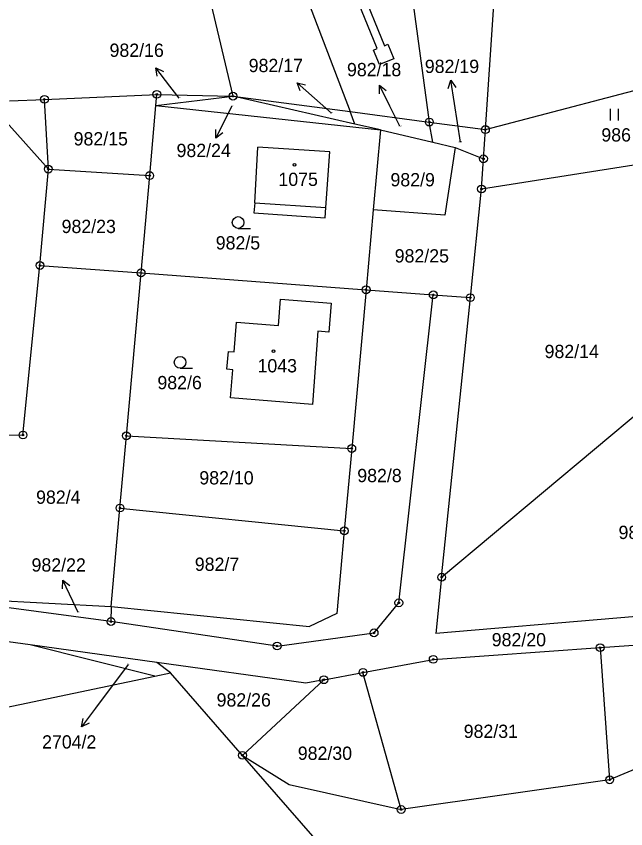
# Model space of a CAD drawing. Extents: x -439246 to -433691, y -1130252 to -1121148.
# Drawn here: x -438051.1 to -437973, y -1124320.3 to -1124216.2 of the extents above; entities that cross this region are included whole.
import ezdxf

# ---------------------------------------------------------------- set-up
doc = ezdxf.new("R2010")
doc.units = 0
for name, color, linetype in [('Vrstva 1', 7, 'Continuous'), ('Vrstva 16', 7, 'Continuous'), ('Vrstva 18', 7, 'Continuous'), ('Vrstva 19', 7, 'Continuous'), ('Vrstva 24', 7, 'Continuous'), ('Vrstva 25', 7, 'Continuous'), ('Vrstva 3', 7, 'Continuous'), ('Vrstva 30', 7, 'Continuous'), ('Vrstva 37', 7, 'Continuous'), ('Vrstva 4', 7, 'Continuous')]:
    doc.layers.add(name, color=color, linetype=linetype)

msp = doc.modelspace()

# ---------------------------------------------------------------- linework, layer by layer
at = {"layer": 'Vrstva 1'}
for points in [[(-438022.56, -1124191.1), (-438008.31, -1124228.46)], [(-438002.2, -1124200.19), (-437998.18, -1124229.8)], [(-437990.99, -1124230.76), (-437988.95, -1124200.08)], [(-438027.12, -1124210.42), (-438023.32, -1124226.48)], [(-437990.99, -1124230.76), (-437965.91, -1124224.17)], [(-438047.47, -1124226.89), (-438033.08, -1124226.25)], [(-438033.2, -1124227.68), (-438033.08, -1124226.25)], [(-438033.2, -1124227.68), (-438023.32, -1124226.48)], [(-438033.08, -1124226.25), (-438023.32, -1124226.48)], [(-438023.32, -1124226.48), (-438008.31, -1124228.46)], [(-438007.7, -1124230.07), (-438023.32, -1124226.48)], [(-438051.94, -1124227.09), (-438047.47, -1124226.89)], [(-438046.97, -1124235.82), (-438047.47, -1124226.89)], [(-438033.99, -1124236.65), (-438033.2, -1124227.68)], [(-438033.2, -1124227.68), (-438004.42, -1124230.8)], [(-438007.7, -1124230.07), (-438008.31, -1124228.46)], [(-438008.31, -1124228.46), (-437998.18, -1124229.8)], [(-438046.97, -1124235.82), (-438053.08, -1124228.96)], [(-437998.18, -1124229.8), (-437990.99, -1124230.76)], [(-437997.73, -1124232.39), (-437998.18, -1124229.8)], [(-438004.42, -1124230.8), (-438007.7, -1124230.07)], [(-438004.42, -1124230.8), (-438005.35, -1124241.04)], [(-438004.42, -1124230.8), (-437997.73, -1124232.39)], [(-437991.24, -1124234.5), (-437990.99, -1124230.76)], [(-438020.54, -1124240.14), (-438020.13, -1124233)], [(-438010.93, -1124233.62), (-438020.13, -1124233)], [(-437997.73, -1124232.39), (-437994.88, -1124233.07)], [(-438011.41, -1124240.75), (-438010.93, -1124233.62)], [(-437994.88, -1124233.07), (-437996.18, -1124241.7)], [(-437994.88, -1124233.07), (-437991.24, -1124234.5)], [(-437991.49, -1124238.36), (-437960.31, -1124233.42)], [(-437991.49, -1124238.36), (-437991.24, -1124234.5)], [(-438048.04, -1124248.16), (-438046.97, -1124235.82)], [(-438046.97, -1124235.82), (-438033.99, -1124236.65)], [(-438035.09, -1124249.11), (-438033.99, -1124236.65)], [(-437992.92, -1124252.28), (-437991.49, -1124238.36)], [(-438020.54, -1124240.14), (-438020.63, -1124241.44)], [(-438011.5, -1124242.05), (-438011.41, -1124240.75)], [(-438005.35, -1124241.04), (-438006.27, -1124251.27)], [(-437996.18, -1124241.7), (-438005.35, -1124241.04)], [(-438020.63, -1124241.44), (-438011.5, -1124242.05)], [(-438050.22, -1124269.87), (-438048.04, -1124248.16)], [(-438048.04, -1124248.16), (-438035.09, -1124249.11)], [(-438036.97, -1124269.97), (-438035.09, -1124249.11)], [(-438035.09, -1124249.11), (-438006.27, -1124251.27)], [(-438006.27, -1124251.27), (-438008.11, -1124271.59)], [(-438006.27, -1124251.27), (-437997.67, -1124251.92)], [(-438017.5, -1124255.86), (-438017.22, -1124252.47)], [(-438017.22, -1124252.47), (-438010.74, -1124253)], [(-438002.08, -1124291.36), (-437997.67, -1124251.92)], [(-437997.67, -1124251.92), (-437992.92, -1124252.28)], [(-437996.6, -1124288.08), (-437992.92, -1124252.28)], [(-438010.74, -1124253), (-438011.05, -1124256.69)], [(-438023.15, -1124259.23), (-438022.88, -1124255.41)], [(-438022.88, -1124255.41), (-438017.5, -1124255.86)], [(-438012.44, -1124256.58), (-438013.13, -1124265.98)], [(-438011.05, -1124256.69), (-438012.44, -1124256.58)], [(-438024.09, -1124261.46), (-438023.9, -1124259.17)], [(-438023.9, -1124259.17), (-438023.15, -1124259.23)], [(-437996.6, -1124288.08), (-437963.96, -1124260.77)], [(-438023.34, -1124261.52), (-438024.09, -1124261.46)], [(-438023.64, -1124265.11), (-438023.34, -1124261.52)], [(-438013.13, -1124265.98), (-438023.64, -1124265.11)], [(-438072.38, -1124269.7), (-438050.22, -1124269.87)], [(-438037.8, -1124279.22), (-438036.97, -1124269.97)], [(-438036.97, -1124269.97), (-438008.11, -1124271.59)], [(-438008.11, -1124271.59), (-438009.06, -1124282.14)], [(-438038.93, -1124291.82), (-438037.8, -1124279.22)], [(-438037.8, -1124279.22), (-438009.06, -1124282.14)], [(-438009.06, -1124282.14), (-438010.02, -1124292.71)], [(-437996.6, -1124288.08), (-437997.33, -1124295.28)], [(-438038.95, -1124293.76), (-438062.93, -1124290.56)], [(-438062.93, -1124290.56), (-438038.93, -1124291.82)], [(-438038.93, -1124291.82), (-438038.95, -1124293.76)], [(-438038.93, -1124291.82), (-438013.54, -1124294.38)], [(-438005.25, -1124295.21), (-438002.08, -1124291.36)], [(-437950.96, -1124291.38), (-437997.33, -1124295.28)], [(-438010.02, -1124292.71), (-438013.54, -1124294.38)], [(-438049.3, -1124296.75), (-438071.18, -1124293.73)], [(-438017.67, -1124296.89), (-438038.95, -1124293.76)], [(-438017.67, -1124296.89), (-438005.25, -1124295.21)], [(-437976.29, -1124297.1), (-437949.33, -1124295.21)], [(-438033.34, -1124300.75), (-438049.3, -1124296.75)], [(-438033.06, -1124299), (-438049.3, -1124296.75)], [(-437997.67, -1124298.6), (-437976.29, -1124297.1)], [(-437976.29, -1124297.1), (-437975.08, -1124314.02)], [(-438006.67, -1124300.27), (-437997.67, -1124298.6)], [(-438031.34, -1124300.33), (-438033.06, -1124299)], [(-438014.01, -1124301.63), (-438033.06, -1124299)], [(-438033.34, -1124300.75), (-438031.34, -1124300.33)], [(-438022.11, -1124310.89), (-438031.34, -1124300.33)], [(-438011.68, -1124301.21), (-438006.67, -1124300.27)], [(-438001.78, -1124317.82), (-438006.67, -1124300.27)], [(-438079.16, -1124310.36), (-438033.34, -1124300.75)], [(-438022.11, -1124310.89), (-438011.68, -1124301.21)], [(-438011.68, -1124301.21), (-438014.01, -1124301.63)], [(-437950.19, -1124303.61), (-437975.08, -1124314.02)], [(-437993.94, -1124343.22), (-438022.11, -1124310.89)], [(-438022.11, -1124310.89), (-438016.12, -1124314.61)], [(-437975.08, -1124314.02), (-438001.78, -1124317.82)], [(-438016.12, -1124314.61), (-438001.78, -1124317.82)]]:
    msp.add_lwpolyline(points, dxfattribs=at)
at = {"layer": 'Vrstva 16'}
for p, q in [((-438031.39, -1124225.22), (-438033.22, -1124222.84)), ((-437994.97, -1124227.41), (-437995.42, -1124224.44)), ((-438012.87, -1124226.75), (-438015.12, -1124224.76)), ((-438003.23, -1124227.77), (-438004.57, -1124225.09)), ((-438024.18, -1124229.16), (-438025.52, -1124231.84)), ((-438043.83, -1124291.16), (-438045.11, -1124288.45)), ((-438040.93, -1124304.86), (-438042.73, -1124307.26))]:
    msp.add_line(p, q, dxfattribs=at)
for points in [[(-438033.01, -1124223.94), (-438033.22, -1124222.84), (-438032.21, -1124223.33)], [(-437995.77, -1124225.51), (-437995.42, -1124224.44), (-437994.78, -1124225.36)], [(-438030.22, -1124226.75), (-438031.39, -1124225.22)], [(-438014.7, -1124225.8), (-438015.12, -1124224.76), (-438014.04, -1124225.05)], [(-438004.57, -1124226.2), (-438004.57, -1124225.09), (-438003.68, -1124225.76)], [(-438010.71, -1124228.67), (-438012.87, -1124226.75)], [(-438023.48, -1124227.75), (-438024.18, -1124229.16)], [(-438001.94, -1124230.33), (-438003.23, -1124227.77)], [(-437994.2, -1124232.38), (-437994.97, -1124227.41)], [(-438024.63, -1124231.17), (-438025.52, -1124231.84), (-438025.52, -1124230.73)], [(-438045.14, -1124289.57), (-438045.11, -1124288.45), (-438044.23, -1124289.14)], [(-438043.15, -1124292.58), (-438043.83, -1124291.16)], [(-438036.73, -1124299.25), (-438040.93, -1124304.86)], [(-438041.73, -1124306.76), (-438042.73, -1124307.26), (-438042.53, -1124306.16)]]:
    msp.add_lwpolyline(points, dxfattribs=at)
at = {"layer": 'Vrstva 24'}
for centre, radius in [((-438033.08, -1124226.25), 0.5), ((-438047.47, -1124226.89), 0.5), ((-438047.47, -1124226.89), 0.1), ((-438033.08, -1124226.25), 0.1), ((-438023.32, -1124226.48), 0.5), ((-438023.32, -1124226.48), 0.1), ((-437998.18, -1124229.8), 0.5), ((-437998.18, -1124229.8), 0.1), ((-437990.99, -1124230.76), 0.5), ((-437990.99, -1124230.76), 0.1), ((-437991.24, -1124234.5), 0.5), ((-437991.24, -1124234.5), 0.1), ((-438046.97, -1124235.82), 0.5), ((-438046.97, -1124235.82), 0.1), ((-438033.99, -1124236.65), 0.5), ((-438033.99, -1124236.65), 0.1), ((-437991.49, -1124238.36), 0.5), ((-437991.49, -1124238.36), 0.1), ((-438048.04, -1124248.16), 0.5), ((-438048.04, -1124248.16), 0.1), ((-438035.09, -1124249.11), 0.5), ((-438035.09, -1124249.11), 0.1), ((-438006.27, -1124251.27), 0.5), ((-438006.27, -1124251.27), 0.1), ((-437997.67, -1124251.92), 0.5), ((-437992.92, -1124252.28), 0.5), ((-437997.67, -1124251.92), 0.1), ((-437992.92, -1124252.28), 0.1), ((-438050.22, -1124269.87), 0.5), ((-438036.97, -1124269.97), 0.5), ((-438050.22, -1124269.87), 0.1), ((-438036.97, -1124269.97), 0.1), ((-438008.11, -1124271.59), 0.5), ((-438008.11, -1124271.59), 0.1), ((-438037.8, -1124279.22), 0.5), ((-438037.8, -1124279.22), 0.1), ((-438009.06, -1124282.14), 0.5), ((-438009.06, -1124282.14), 0.1), ((-437996.6, -1124288.08), 0.5), ((-437996.6, -1124288.08), 0.1), ((-438002.08, -1124291.36), 0.5), ((-438002.08, -1124291.36), 0.1), ((-438038.95, -1124293.76), 0.5), ((-438038.95, -1124293.76), 0.1), ((-438005.25, -1124295.21), 0.5), ((-438005.25, -1124295.21), 0.1), ((-438017.67, -1124296.89), 0.5), ((-438017.67, -1124296.89), 0.1), ((-437976.29, -1124297.1), 0.5), ((-437976.29, -1124297.1), 0.1), ((-437997.67, -1124298.6), 0.5), ((-437997.67, -1124298.6), 0.1), ((-438006.67, -1124300.27), 0.5), ((-438006.67, -1124300.27), 0.1), ((-438011.68, -1124301.21), 0.5), ((-438011.68, -1124301.21), 0.1), ((-438022.11, -1124310.89), 0.5), ((-438022.11, -1124310.89), 0.1), ((-437975.08, -1124314.02), 0.5), ((-437975.08, -1124314.02), 0.1), ((-438001.78, -1124317.82), 0.5), ((-438001.78, -1124317.82), 0.1)]:
    msp.add_circle(centre, radius, dxfattribs=at)
at = {"layer": 'Vrstva 25'}
for p, q in [((-437974.95, -1124229.59), (-437974.95, -1124228.09)), ((-437973.95, -1124229.59), (-437973.95, -1124228.09)), ((-438022.66, -1124243.41), (-438021.06, -1124243.41)), ((-438030.09, -1124261.31), (-438028.49, -1124261.31))]:
    msp.add_line(p, q, dxfattribs=at)
for centre, radius in [((-438015.43, -1124235.28), 0.175), ((-438022.66, -1124242.66), 0.75), ((-438018.12, -1124259.15), 0.175), ((-438030.09, -1124260.56), 0.75)]:
    msp.add_circle(centre, radius, dxfattribs=at)
at = {"layer": 'Vrstva 3'}
for points in [[(-438020.54, -1124240.14), (-438020.13, -1124233)], [(-438010.93, -1124233.62), (-438020.13, -1124233)], [(-438011.41, -1124240.75), (-438010.93, -1124233.62)], [(-438020.54, -1124240.14), (-438011.41, -1124240.75)], [(-438017.5, -1124255.86), (-438017.22, -1124252.47)], [(-438017.22, -1124252.47), (-438010.74, -1124253)], [(-438010.74, -1124253), (-438011.05, -1124256.69)], [(-438023.15, -1124259.23), (-438022.88, -1124255.41)], [(-438022.88, -1124255.41), (-438017.5, -1124255.86)], [(-438012.44, -1124256.58), (-438013.13, -1124265.98)], [(-438011.05, -1124256.69), (-438012.44, -1124256.58)], [(-438024.09, -1124261.46), (-438023.9, -1124259.17)], [(-438023.9, -1124259.17), (-438023.15, -1124259.23)], [(-438023.34, -1124261.52), (-438024.09, -1124261.46)], [(-438023.64, -1124265.11), (-438023.34, -1124261.52)], [(-438013.13, -1124265.98), (-438023.64, -1124265.11)]]:
    msp.add_lwpolyline(points, dxfattribs=at)
at = {"layer": 'Vrstva 30'}
msp.add_lwpolyline([(-438013.93, -1124198.11), (-438019.08, -1124200.21), (-438019.44, -1124199.28), (-438013.85, -1124197), (-438005.19, -1124193.43), (-438004.78, -1124194.34), (-438013.01, -1124197.73), (-438003.93, -1124220.02), (-438003.47, -1124219.83), (-438002.72, -1124221.68), (-438004.57, -1124222.43), (-438005.32, -1124220.58), (-438004.86, -1124220.39), (-438013.93, -1124198.11)], dxfattribs=at)
at = {"layer": 'Vrstva 37'}
for centre in [(-438015.43, -1124235.28), (-438018.12, -1124259.15)]:
    msp.add_circle(centre, 0.175, dxfattribs=at)
at = {"layer": 'Vrstva 4'}
msp.add_lwpolyline([(-438020.54, -1124240.14), (-438011.41, -1124240.75)], dxfattribs=at)

# ---------------------------------------------------------------- texts
at = {"layer": 'Vrstva 16'}
for s, p in [('982/16', (-438039.13, -1124221.45)), ('982/17', (-438021.31, -1124223.4)), ('982/18', (-438008.72, -1124223.93)), ('982/19', (-437998.75, -1124223.51)), ('982/24', (-438030.55, -1124234.28)), ('982/22', (-438049.12, -1124287.36)), ('2704/2', (-438047.77, -1124310.02))]:
    msp.add_text(s, height=1.7, dxfattribs=at).set_placement(p)
at = {"layer": 'Vrstva 18'}
for s, height, p in [('982/16', 0.1, (-438030.43, -1124226.75)), ('982/24', 0.1, (-438023.71, -1124227.75)), ('982/17', 0.1, (-438010.92, -1124228.67)), ('982/18', 0.1, (-438002.15, -1124230.33)), ('986', 1.7, (-437976.14, -1124232.29)), ('982/15', 1.7, (-438043.73, -1124232.79)), ('982/19', 0.1, (-437994.41, -1124232.38)), ('982/9', 1.7, (-438003.15, -1124238.03)), ('982/23', 1.7, (-438045.27, -1124244.01)), ('982/5', 1.7, (-438025.53, -1124246.11)), ('982/25', 1.7, (-438002.61, -1124247.78)), ('982/14', 1.7, (-437983.41, -1124260.02)), ('982/6', 1.7, (-438033, -1124264.01)), ('982/10', 1.7, (-438027.63, -1124276.2)), ('982/8', 1.7, (-438007.4, -1124275.91)), ('982/4', 1.7, (-438048.54, -1124278.68)), ('982/21', 1.7, (-437973.94, -1124283.19)), ('982/7', 1.7, (-438028.21, -1124287.27)), ('982/22', 0.1, (-438043.39, -1124292.58)), ('982/20', 1.7, (-437990.18, -1124296.93)), ('2704/2', 0.1, (-438036.96, -1124299.25)), ('982/26', 1.7, (-438025.42, -1124304.64)), ('982/31', 1.7, (-437993.77, -1124308.66)), ('982/30', 1.7, (-438015.02, -1124311.47))]:
    msp.add_text(s, height=height, dxfattribs=at).set_placement(p)
at = {"layer": 'Vrstva 19'}
for s, p in [('1075', (-438017.5, -1124237.98)), ('1043', (-438020.18, -1124261.85))]:
    msp.add_text(s, height=1.7, dxfattribs=at).set_placement(p)

doc.saveas('drawing.dxf')
